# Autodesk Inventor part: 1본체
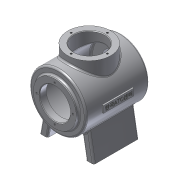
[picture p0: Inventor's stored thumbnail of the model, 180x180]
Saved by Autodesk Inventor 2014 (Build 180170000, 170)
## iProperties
Created: 2015-01
Part Number: 1본체
Material: 알루미늄 6061
Document SubType Name: Modeling
Designer: L-10
Density: 2.71 g/cm^3
Appearance: 알루미늄 - 평지
Mass: 953.119 g
Surface Area: 1057.99 cm^2
Volume: 351.704 cm^3
Author: L-10
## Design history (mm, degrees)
sketch "스케치1"
  geometry: C1 r 50 at (0, 0); 1 further point
  constraints: 1 centre point, 1 coincident
  dimensions: "d0" = 100 diameter of C1
extrude "돌출1" new body sketch "스케치1" distance "d1" = 112; taper "d2" = 0 deg
sketch "스케치2"
  geometry: C1 r 50 at (0, 0) reference; C2 r 38 at (0, 0)
  constraints: 1 centre point, 1 coincident
  dimensions: "d3" = 76 diameter of C2
extrude "돌출2" join sketch "스케치2" distance "d4" = 5; taper "d5" = 0 deg
node "작업 평면1"
node "작업 평면2"
sketch "스케치3"
  geometry: L1 (50, 112)-(-50, 112) reference; L2 (-50, 0)-(50, 0) reference; L3 (-50, 0)-(-50, 112) reference; L4 (50, 0)-(50, 112) reference; C1 r 38 at (0, 56); 1 further point
  constraints: 1 centre point
  dimensions: "d7" = 76 diameter of C1; "d8" = 112 distance of L3.start L3.end (derived); "d10" = 0 horizontal distance of point (0, 0) C1.centre; "d11" = 56 distance from line of L1 C1.centre (= 0.5 x d8)
extrude "돌출3" join sketch "스케치3" stored distance "d12" = 5; taper "d13" = 0 deg
sketch "스케치5"
  geometry: L1 (-39.336, 30.865)-(-48, 80); L2 (-48, 80)-(-34, 80); L3 (-34, 80)-(-27.282, 41.901); A1 r 50 centre (0, 0) between (-27.282, 41.901) and (-39.336, 30.865) reference; A2 r 50 centre (0, 0) between (-27.282, 41.901) and (-39.336, 30.865); 1 further point
  constraints: 6 end point, 4 point on circle, 1 centre point, 1 concentric, 1 horizontal, 1 parallel
  dimensions: "d14" = 100 deg angle of L2 L1; "d15" = 80 deg angle of L2 L3 (derived); "d16" = 14 distance of L1.end L2.end; "d17" = 80 distance from line of L2 point (0, 0); "d18" = 48 horizontal distance of point (0, 0) L1.end
extrude "돌출4" join sketch "스케치5" stored distance "d19" = 80; taper "d20" = 0 deg
node "작업 평면3"
sketch "스케치6"
  geometry: L1 (29, 6)-(83, 6); L2 (83, 6)-(83, -6); L3 (83, -6)-(29, -6); L4 (29, -6)-(29, 6); L5 (0, 50)-(112, 50) reference; L6 (0, 50)-(0, -50) reference; L7 (112, -50)-(112, 50) reference; L8 (0, -50)-(112, -50) reference; 1 further point
  constraints: 8 end point, 2 parallel, 1 horizontal, 1 perpendicular
  dimensions: "d22" = 54 distance of L1.start L1.end; "d23" = 12 distance of L3.end L1.start; "d24" = 6 distance from line of point (0, 0) L1 (= 0.5 x d23); "d25" = 112 distance of L5.start L5.end (derived); "d26" = 29 distance between parallel lines of L6 L4 (= -0.5 x d22 + 0.5 x d25)
extrude "돌출5" join sketch "스케치6" stored distance "d27" = 80; taper "d28" = 0 deg
sketch "스케치7"
  geometry: L1 (-6, 29)-(-6, 83) reference; L2 (6, 29)-(-6, 29) reference; 3 further points
  constraints: 1 other
  dimensions: "d29" = 54 distance of L1.start L1.end (derived); "d30" = 12 distance of L1.end point (6, 83) (derived); "d31" = 6 distance from line of L1 point (0, 56) (= 0.5 x d30); "d32" = 27 distance from line of L2 point (0, 56) (= 0.5 x d29)
feature "엠보싱1" sketch "스케치7" dims "d33" = 0.5, "d34" = 0
hole "구멍1" diameter "d37" = 54; stored, may be unused: countersink angle "d41" = 90 deg, drill point angle "d43" = 118 deg; dims "d35" = 10, "d36" = 10, "d38" = 6, "d39" = 4, "d40" = 2, "d42" = 8
node "작업 평면4"
sketch "스케치9"
  geometry: C1 r 45 at (0, 0); 1 further point
  constraints: 1 centre point, 1 coincident
  dimensions: "d48" = 90 diameter of C1
extrude "돌출7" cut sketch "스케치9" distance "d49" = 97; taper "d50" = 0 deg
hole "구멍2" diameter "d53" = 54; stored, may be unused: countersink angle "d57" = 90 deg, drill point angle "d59" = 118 deg; dims "d51" = 10, "d52" = 10, "d54" = 6, "d55" = 4, "d56" = 2, "d58" = 8
sketch "스케치10"
  geometry: C1 r 27 at (0, 0) reference; 2 further points
  dimensions: "d60" = 0 horizontal distance of point (0, 32) C1.centre; "d61" = 32 distance of C1.centre point (0, 32)
hole "구멍3" sketch "스케치10" at (0, 32) diameter "d62" = 3.242; stored, may be unused: countersink angle "d66" = 90 deg, drill point angle "d68" = 118 deg; dims "d63" = 8, "d64" = 4, "d65" = 2, "d67" = 10
sketch "스케치11"
  geometry: C1 r 27 at (0, 0) reference; 1 further point
  dimensions: "d72" = 0 horizontal distance of point (0, 32) C1.centre; "d73" = 32 distance of C1.centre point (0, 32)
hole "구멍4" sketch "스케치11" at (0, 32) diameter "d74" = 3.242; stored, may be unused: countersink angle "d78" = 90 deg, drill point angle "d80" = 118 deg; dims "d75" = 8, "d76" = 4, "d77" = 2, "d79" = 10
chamfer "모따기1" distance "d84" = 1; stored, may be unused: second distance "d85" = 2, angle "d86" = 45 deg
chamfer "모따기2" distance "d87" = 1; stored, may be unused: second distance "d88" = 2, angle "d89" = 45 deg
chamfer "모따기3" distance "d90" = 1; stored, may be unused: second distance "d91" = 2, angle "d92" = 45 deg
fillet "모깎기1" dims "d93" = 3
fillet "모깎기2" dims "d94" = 3
fillet "모깎기3" dims "d95" = 3
fillet "모깎기4" dims "d96" = 3
fillet "모깎기5" dims "d97" = 3
fillet "모깎기6" dims "d98" = 3
node "솔리드1"
mirror "대칭1"
mirror "대칭2"
pattern_circular "원형 패턴1" dims angle "d70" = 360 deg
pattern_circular "원형 패턴2" dims angle "d82" = 360 deg
mirror "대칭3"
node "투영된 루프1"
other parameters: "d6" = 62, "d21" = 52, "d47" = -7
